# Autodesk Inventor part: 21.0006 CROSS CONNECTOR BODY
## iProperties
Created: 2009-01
Part Number: 21.0006 CROSS CONNECTOR BODY
Document SubType Name: Modeling
Designer: Administrator
Density: 7.85 g/cm^3
Material: Steel
Mass: 32.6475 g
Surface Area: 23.7512 cm^2
Volume: 4.15891 cm^3
Author: Administrator
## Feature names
1. Base1
